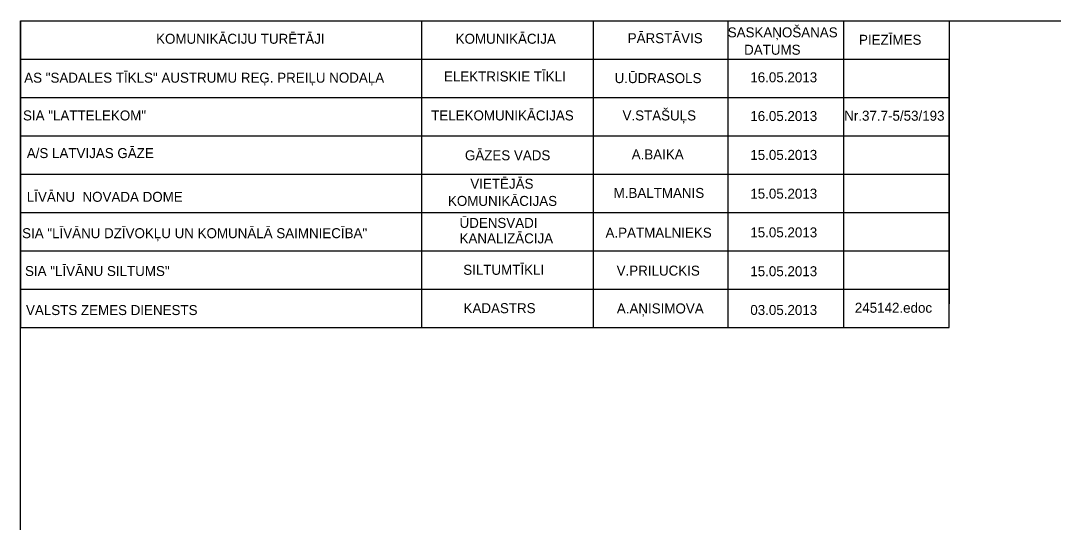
# Model space of a CAD drawing. Extents: x 634272 to 634544, y 247463 to 247653.
# Drawn here: x 634272.1 to 634375.4, y 247602.8 to 247653 of the extents above; entities that cross this region are included whole.
import ezdxf

# ---------------------------------------------------------------- set-up
doc = ezdxf.new("R2010")
doc.units = 0
doc.layers.add('RAMI_PLAN_####_TKST_#', color=7, linetype='Continuous')

msp = doc.modelspace()

# ---------------------------------------------------------------- linework, layer by layer
at = {"layer": 'RAMI_PLAN_####_TKST_#'}
for p, q in [((634272.07, 247622.28), (634272.07, 247653)), ((634272.07, 247653), (634365, 247653)), ((634272.07, 247653), (634272.07, 247622.28)), ((634312.18, 247653), (634312.18, 247622.28)), ((634329.38, 247653), (634329.38, 247622.28)), ((634342.9, 247622.28), (634342.9, 247653)), ((634354.47, 247622.28), (634354.47, 247653)), ((634365, 247653), (634365, 247624.65)), ((634272.07, 247649.16), (634365, 247649.16)), ((634365, 247624.65), (634365, 247649.16)), ((634272.07, 247645.32), (634365, 247645.32)), ((634272.07, 247641.48), (634365, 247641.48)), ((634272.07, 247637.64), (634365, 247637.64)), ((634272.07, 247633.8), (634365, 247633.8)), ((634272.07, 247629.96), (634365, 247629.96)), ((634365, 247622.28), (634365, 247628.49)), ((634272.07, 247626.12), (634365, 247626.12)), ((634272.07, 247622.28), (634365, 247622.28))]:
    msp.add_line(p, q, dxfattribs=at)
msp.add_lwpolyline([(634272.07, 247653), (634543.91, 247653), (634543.91, 247462.95), (634272.07, 247462.95)], close=True, dxfattribs=at)

# ---------------------------------------------------------------- texts
for s, p in [('KOMUNIKĀCIJU TURĒTĀJI', (634285.63, 247650.69)), ('KOMUNIKĀCIJA', (634315.61, 247650.69)), ('PĀRSTĀVIS', (634332.83, 247650.75)), ('SASKAŅOŠANAS', (634342.84, 247651.33)), ('PIEZĪMES', (634355.98, 247650.59)), ('DATUMS', (634344.48, 247649.59)), ('AS "SADALES TĪKLS" AUSTRUMU REĢ. PREIĻU NODAĻA', (634272.43, 247646.79)), ('ELEKTRISKIE TĪKLI', (634314.44, 247646.92)), ('U.ŪDRASOLS', (634331.52, 247646.75)), ('16.05.2013', (634345.1, 247646.83)), ('SIA "LATTELEKOM"', (634272.31, 247643.01)), ('TELEKOMUNIKĀCIJAS', (634313.16, 247643.01)), ('V.STAŠUĻS', (634332.31, 247643.01)), ('16.05.2013', (634345.1, 247642.95)), ('Nr.37.7-5/53/193', (634354.5, 247642.98)), ('A/S LATVIJAS GĀZE', (634272.69, 247639.24)), ('GĀZES VADS', (634316.54, 247639.02)), ('A.BAIKA', (634333.23, 247639.11)), ('15.05.2013', (634345.1, 247639.06)), ('VIETĒJĀS', (634317.08, 247636.17)), ('LĪVĀNU  NOVADA DOME', (634272.69, 247634.86)), ('KOMUNIKĀCIJAS', (634314.84, 247634.45)), ('M.BALTMANIS', (634331.42, 247635.25)), ('15.05.2013', (634345.1, 247635.18)), ('ŪDENSVADI', (634316, 247632.25)), ('SIA "LĪVĀNU DZĪVOKĻU UN KOMUNĀLĀ SAIMNIECĪBA"', (634272.22, 247631.22)), ('A.PATMALNIEKS', (634330.61, 247631.27)), ('15.05.2013', (634345.1, 247631.3)), ('KANALIZĀCIJA', (634316, 247630.7)), ('SIA "LĪVĀNU SILTUMS"', (634272.51, 247627.43)), ('SILTUMTĪKLI', (634316.37, 247627.55)), ('V.PRILUCKIS', (634331.72, 247627.47)), ('15.05.2013', (634345.1, 247627.41)), ('VALSTS ZEMES DIENESTS', (634272.61, 247623.52)), ('KADASTRS', (634316.4, 247623.71)), ('A.AŅISIMOVA', (634331.74, 247623.68)), ('03.05.2013', (634345.1, 247623.53)), ('245142.edoc', (634355.56, 247623.75))]:
    msp.add_text(s, height=1, dxfattribs=at).set_placement(p)

doc.saveas('drawing.dxf')
